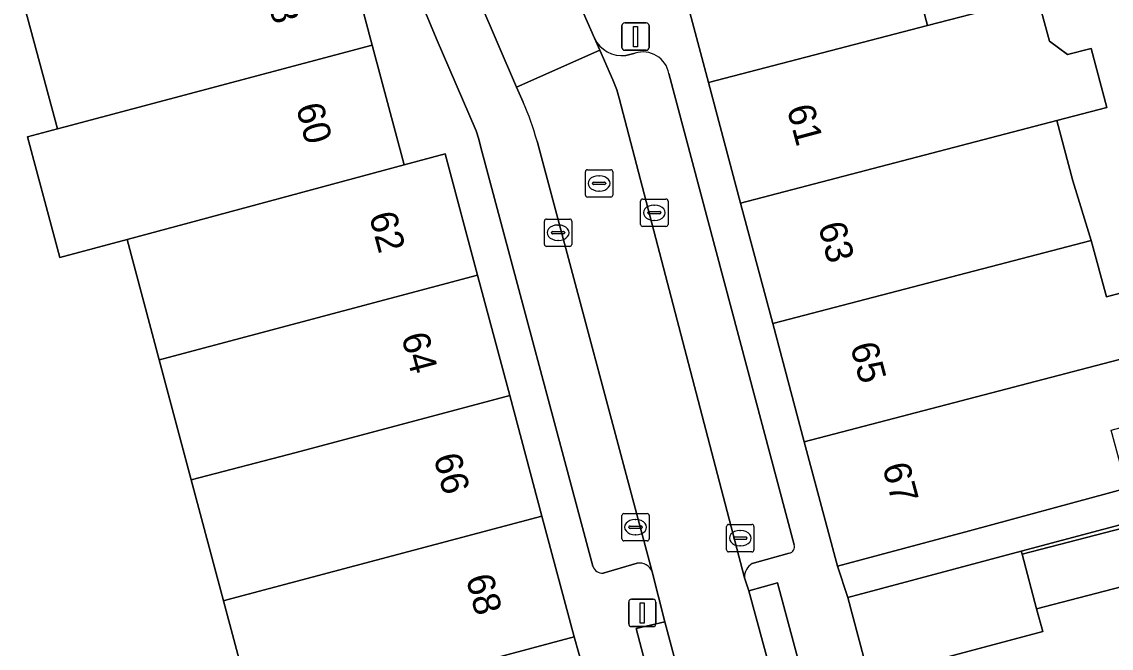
# Model space of a CAD drawing. Extents: x 162542 to 163147, y 380779 to 381521.
# Drawn here: x 162882.07 to 162921.91, y 380905.79 to 380928.7 of the extents above; entities that cross this region are included whole.
import ezdxf

# ---------------------------------------------------------------- set-up
doc = ezdxf.new("R2010")
doc.units = 0
for name, color, linetype in [('IMGEO_Erf', 7, 'Continuous'), ('IMGEO_Kolk', 7, 'Continuous'), ('IMGEO_Lichtmast', 7, 'Continuous'), ('IMGEO_Pand', 7, 'Continuous'), ('IMGEO_Pand_nummerreeks', 7, 'Continuous'), ('IMGEO_Parkeervlak_open', 7, 'Continuous'), ('IMGEO_Rijbaan_lokaal_open', 7, 'Continuous'), ('IMGEO_Rioolput', 7, 'Continuous'), ('IMGEO_Voetpad_open', 7, 'Continuous')]:
    doc.layers.add(name, color=color, linetype=linetype)

msp = doc.modelspace()

# ---------------------------------------------------------------- linework, layer by layer
at = {"layer": 'IMGEO_Erf'}
for points in [[(162890.631, 380903.092), (162889.449, 380907.52), (162888.269, 380911.939), (162887.097, 380916.331), (162885.922, 380920.733), (162883.467, 380920.075), (162882.284, 380924.488), (162883.382, 380924.781), (162882.176, 380929.207), (162880.985, 380933.581)], [(162914.667, 380930.542), (162915.195, 380928.561), (162919.214, 380929.61), (162919.648, 380927.984), (162920.311, 380927.498), (162921.176, 380927.724), (162921.753, 380925.561), (162919.917, 380925.082), (162920.505, 380922.876), (162921.182, 380920.701), (162921.733, 380918.636), (162923.471, 380919.099)], [(162945.042, 380916.372), (162918.622, 380909.332), (162918.65, 380909.228), (162923.026, 380910.365)], [(162923.547, 380908.361), (162919.184, 380907.225), (162919.405, 380906.398), (162913.056, 380904.704), (162914.099, 380900.681), (162917.41, 380901.57), (162920.403, 380902.374), (162920.845, 380900.718), (162926.157, 380902.145)]]:
    msp.add_lwpolyline(points, dxfattribs=at)
at = {"layer": 'IMGEO_Kolk'}
for p, q in [((162904.701, 380921.287), (162904.701, 380922.139)), ((162904.776, 380922.213), (162905.628, 380922.213)), ((162905.702, 380922.139), (162905.702, 380921.287)), ((162904.96, 380921.707), (162904.96, 380921.719)), ((162905.398, 380921.67), (162905, 380921.67)), ((162905.003, 380921.756), (162905.401, 380921.756)), ((162905.189, 380921.993), (162905.214, 380921.993)), ((162905.444, 380921.719), (162905.444, 380921.707)), ((162901.182, 380920.557), (162901.182, 380921.409)), ((162901.257, 380921.483), (162902.109, 380921.483)), ((162901.67, 380921.263), (162901.695, 380921.263)), ((162902.183, 380921.409), (162902.183, 380920.557)), ((162905.212, 380921.433), (162905.187, 380921.433)), ((162901.441, 380920.977), (162901.441, 380920.989)), ((162901.879, 380920.94), (162901.481, 380920.94)), ((162901.484, 380921.026), (162901.882, 380921.026)), ((162901.925, 380920.989), (162901.925, 380920.977)), ((162905.628, 380921.213), (162904.776, 380921.213)), ((162902.109, 380920.483), (162901.257, 380920.483)), ((162901.693, 380920.703), (162901.668, 380920.703)), ((162904.015, 380909.786), (162904.015, 380910.638)), ((162904.09, 380910.712), (162904.942, 380910.712)), ((162905.016, 380910.638), (162905.016, 380909.786)), ((162904.274, 380910.206), (162904.274, 380910.218)), ((162904.712, 380910.169), (162904.314, 380910.169)), ((162904.317, 380910.255), (162904.715, 380910.255)), ((162904.503, 380910.492), (162904.528, 380910.492)), ((162904.758, 380910.218), (162904.758, 380910.206)), ((162907.845, 380909.385), (162907.845, 380910.237)), ((162907.92, 380910.311), (162908.772, 380910.311)), ((162908.846, 380910.237), (162908.846, 380909.385)), ((162904.942, 380909.712), (162904.09, 380909.712)), ((162904.526, 380909.932), (162904.501, 380909.932)), ((162908.104, 380909.805), (162908.104, 380909.817)), ((162908.542, 380909.768), (162908.144, 380909.768)), ((162908.147, 380909.854), (162908.545, 380909.854)), ((162908.333, 380910.091), (162908.358, 380910.091)), ((162908.588, 380909.817), (162908.588, 380909.805)), ((162908.772, 380909.311), (162907.92, 380909.311)), ((162908.356, 380909.531), (162908.331, 380909.531))]:
    msp.add_line(p, q, dxfattribs=at)
for points in [[(162904.701, 380921.287), (162904.701, 380922.139)], [(162904.776, 380922.213), (162905.628, 380922.213)], [(162905.702, 380922.139), (162905.702, 380921.287)], [(162901.182, 380920.557), (162901.182, 380921.409)], [(162901.257, 380921.483), (162902.109, 380921.483)], [(162902.183, 380921.409), (162902.183, 380920.557)], [(162905.628, 380921.213), (162904.776, 380921.213)], [(162902.109, 380920.483), (162901.257, 380920.483)], [(162904.015, 380909.786), (162904.015, 380910.638)], [(162904.09, 380910.712), (162904.942, 380910.712)], [(162905.016, 380910.638), (162905.016, 380909.786)], [(162907.845, 380909.385), (162907.845, 380910.237)], [(162907.92, 380910.311), (162908.772, 380910.311)], [(162908.846, 380910.237), (162908.846, 380909.385)], [(162904.942, 380909.712), (162904.09, 380909.712)], [(162908.772, 380909.311), (162907.92, 380909.311)]]:
    msp.add_lwpolyline(points, dxfattribs=at)
for centre, radius, start, end in [((162904.778, 380922.137), 0.0765, 91.552, 178.448), ((162904.778, 380922.137), 0.0765, 91.552, 178.448), ((162905.626, 380922.137), 0.0765, 1.552, 88.448), ((162905.626, 380922.137), 0.0765, 1.552, 88.448), ((162905, 380921.716), 0.0403, 85.8775, 175.7526), ((162904.997, 380921.706), 0.0366, 178.938, 274.7102), ((162905.401, 380921.713), 0.043, 264.8664, 352.4533), ((162905.405, 380921.718), 0.0386, 1.7309, 96.639), ((162901.259, 380921.407), 0.0765, 91.552, 178.448), ((162901.259, 380921.407), 0.0765, 91.552, 178.448), ((162902.107, 380921.407), 0.0765, 1.552, 88.448), ((162902.107, 380921.407), 0.0765, 1.552, 88.448), ((162904.778, 380921.289), 0.0765, 181.552, 268.448), ((162904.778, 380921.289), 0.0765, 181.552, 268.448), ((162905.626, 380921.289), 0.0765, 271.552, 358.448), ((162905.626, 380921.289), 0.0765, 271.552, 358.448), ((162901.481, 380920.986), 0.0403, 85.8775, 175.7526), ((162901.478, 380920.976), 0.0366, 178.938, 274.7102), ((162901.882, 380920.983), 0.043, 264.8664, 352.4533), ((162901.886, 380920.988), 0.0386, 1.7309, 96.639), ((162901.259, 380920.559), 0.0765, 181.552, 268.448), ((162901.259, 380920.559), 0.0765, 181.552, 268.448), ((162902.107, 380920.559), 0.0765, 271.552, 358.448), ((162902.107, 380920.559), 0.0765, 271.552, 358.448), ((162904.092, 380910.636), 0.0765, 91.552, 178.448), ((162904.092, 380910.636), 0.0765, 91.552, 178.448), ((162904.94, 380910.636), 0.0765, 1.552, 88.448), ((162904.94, 380910.636), 0.0765, 1.552, 88.448), ((162904.314, 380910.215), 0.0403, 85.8775, 175.7526), ((162904.311, 380910.205), 0.0366, 178.938, 274.7102), ((162904.715, 380910.212), 0.043, 264.8664, 352.4533), ((162904.719, 380910.217), 0.0386, 1.7309, 96.639), ((162907.922, 380910.235), 0.0765, 91.552, 178.448), ((162907.922, 380910.235), 0.0765, 91.552, 178.448), ((162908.77, 380910.235), 0.0765, 1.552, 88.448), ((162908.77, 380910.235), 0.0765, 1.552, 88.448), ((162904.092, 380909.788), 0.0765, 181.552, 268.448), ((162904.092, 380909.788), 0.0765, 181.552, 268.448), ((162904.94, 380909.788), 0.0765, 271.552, 358.448), ((162904.94, 380909.788), 0.0765, 271.552, 358.448), ((162908.144, 380909.814), 0.0403, 85.8775, 175.7526), ((162908.141, 380909.804), 0.0366, 178.938, 274.7102), ((162908.545, 380909.811), 0.043, 264.8664, 352.4533), ((162908.549, 380909.816), 0.0386, 1.7309, 96.639), ((162907.922, 380909.387), 0.0765, 181.552, 268.448), ((162907.922, 380909.387), 0.0765, 181.552, 268.448), ((162908.77, 380909.387), 0.0765, 271.552, 358.448), ((162908.77, 380909.387), 0.0765, 271.552, 358.448)]:
    msp.add_arc(centre, radius, start, end, dxfattribs=at)
for centre, major_axis, ratio, start_param, end_param in [((162905.188, 380921.713), (-0.387, 0.002), 0.722429, 4.712389, 7.853982), ((162905.213, 380921.713), (-0.39, 0.002), 0.717154, 1.570796, 4.712389), ((162901.669, 380920.983), (-0.387, 0.002), 0.722429, 4.712389, 7.853982), ((162901.694, 380920.983), (-0.39, 0.002), 0.717154, 1.570796, 4.712389), ((162904.502, 380910.212), (-0.387, 0.002), 0.722429, 4.712389, 7.853982), ((162904.527, 380910.212), (-0.39, 0.002), 0.717154, 1.570796, 4.712389), ((162908.332, 380909.811), (-0.387, 0.002), 0.722429, 4.712389, 7.853982), ((162908.357, 380909.811), (-0.39, 0.002), 0.717154, 1.570796, 4.712389)]:
    msp.add_ellipse(centre, major_axis=major_axis, ratio=ratio, start_param=start_param, end_param=end_param, dxfattribs=at)
at = {"layer": 'IMGEO_Lichtmast'}
for p, q in [((162904.019, 380927.755), (162904.019, 380928.555)), ((162904.019, 380928.555), (162904.019, 380927.755)), ((162904.119, 380928.655), (162904.909, 380928.655)), ((162904.909, 380928.655), (162904.119, 380928.655)), ((162905.009, 380928.555), (162905.009, 380927.755)), ((162905.009, 380927.755), (162905.009, 380928.555)), ((162904.909, 380927.655), (162904.119, 380927.655)), ((162904.119, 380927.655), (162904.909, 380927.655)), ((162904.266, 380906.676), (162904.266, 380907.476)), ((162904.266, 380907.476), (162904.266, 380906.676)), ((162904.366, 380907.576), (162905.156, 380907.576)), ((162905.156, 380907.576), (162904.366, 380907.576)), ((162905.256, 380907.476), (162905.256, 380906.676)), ((162905.256, 380906.676), (162905.256, 380907.476)), ((162905.156, 380906.576), (162904.366, 380906.576)), ((162904.366, 380906.576), (162905.156, 380906.576))]:
    msp.add_line(p, q, dxfattribs=at)
for points in [[(162904.439, 380928.53), (162904.589, 380928.53), (162904.589, 380927.78), (162904.439, 380927.78), (162904.439, 380928.53)], [(162904.686, 380907.451), (162904.836, 380907.451), (162904.836, 380906.701), (162904.686, 380906.701), (162904.686, 380907.451)]]:
    msp.add_lwpolyline(points, dxfattribs=at)
for centre, start, end in [((162904.119, 380928.555), 90, 180), ((162904.119, 380928.555), 90, 180), ((162904.909, 380928.555), 0, 90), ((162904.909, 380928.555), 360, 90), ((162904.119, 380927.755), 180, 270), ((162904.119, 380927.755), 180, 270), ((162904.909, 380927.755), 270, 0), ((162904.909, 380927.755), 270, 0), ((162904.366, 380907.476), 90, 180), ((162904.366, 380907.476), 90, 180), ((162905.156, 380907.476), 0, 90), ((162905.156, 380907.476), 360, 90), ((162904.366, 380906.676), 180, 270), ((162904.366, 380906.676), 180, 270), ((162905.156, 380906.676), 270, 0), ((162905.156, 380906.676), 270, 0)]:
    msp.add_arc(centre, 0.1, start, end, dxfattribs=at)
at = {"layer": 'IMGEO_Pand'}
for points in [[(162906.008, 380930.874), (162907.183, 380926.47), (162915.195, 380928.561), (162914.667, 380930.542), (162918.176, 380931.478), (162917.534, 380933.883)], [(162894.884, 380927.843), (162893.708, 380932.249), (162882.176, 380929.207), (162883.382, 380924.781), (162883.653, 380924.853)], [(162921.176, 380927.724), (162920.311, 380927.498), (162919.648, 380927.984), (162919.214, 380929.61), (162915.195, 380928.561), (162907.183, 380926.47), (162908.358, 380922.065), (162919.917, 380925.082), (162921.753, 380925.561)], [(162885.922, 380920.733), (162888.504, 380921.425), (162896.052, 380923.468), (162894.884, 380927.843), (162883.653, 380924.853), (162883.382, 380924.781), (162882.284, 380924.488), (162883.467, 380920.075)], [(162919.917, 380925.082), (162908.358, 380922.065), (162909.533, 380917.661), (162921.182, 380920.701), (162920.505, 380922.876)], [(162885.922, 380920.733), (162887.097, 380916.331), (162887.236, 380916.369), (162898.741, 380919.432), (162897.556, 380923.869), (162896.052, 380923.468), (162888.504, 380921.425)], [(162921.182, 380920.701), (162909.533, 380917.661), (162910.687, 380913.334), (162924.075, 380916.835), (162923.471, 380919.099), (162921.733, 380918.636)], [(162888.269, 380911.939), (162892.108, 380912.947), (162899.917, 380915.027), (162898.741, 380919.432), (162887.236, 380916.369), (162887.097, 380916.331)], [(162924.075, 380916.835), (162910.687, 380913.334), (162911.899, 380908.789), (162916.731, 380910.078), (162919.873, 380910.937), (162922.48, 380911.639), (162921.913, 380913.766), (162922.957, 380914.045), (162924.696, 380914.509)], [(162889.449, 380907.52), (162889.573, 380907.553), (162901.093, 380910.62), (162899.917, 380915.027), (162892.108, 380912.947), (162888.269, 380911.939)], [(162889.449, 380907.52), (162890.631, 380903.092), (162897.443, 380904.91), (162902.273, 380906.2), (162901.093, 380910.62), (162889.573, 380907.553)], [(162924.873, 380910.845), (162923.026, 380910.365), (162918.65, 380909.228), (162919.184, 380907.225), (162923.547, 380908.361), (162925.406, 380908.845)], [(162919.184, 380907.225), (162918.65, 380909.228), (162918.622, 380909.332), (162912.273, 380907.638), (162913.056, 380904.704), (162919.405, 380906.398)]]:
    msp.add_lwpolyline(points, close=True, dxfattribs=at)
at = {"layer": 'IMGEO_Parkeervlak_open'}
for points in [[(162863.623, 381056.326), (162869.619, 381033.902), (162872.201, 381021.07), (162882.251, 380983.223), (162896.332, 380930.722), (162896.579, 380929.758), (162896.835, 380929.036), (162897.228, 380928.095), (162898.683, 380924.706), (162898.786, 380924.4), (162898.843, 380924.15), (162902.951, 380908.79)], [(162900.404, 380925.757), (162900.167, 380926.307), (162898.784, 380929.52), (162898.75, 380929.6)], [(162903.018, 380928.1), (162903.211, 380927.653), (162903.679, 380926.571), (162903.826, 380926.209), (162903.922, 380925.897), (162908.496, 380908.364)], [(162904.497, 380927.552), (162904.154, 380927.467)], [(162910.311, 380909.571), (162905.736, 380926.804)], [(162905.118, 380908.579), (162900.912, 380924.329)], [(162908.786, 380908.882), (162910.137, 380909.259)], [(162903.337, 380908.533), (162904.57, 380908.891)]]:
    msp.add_lwpolyline(points, dxfattribs=at)
for centre, radius, start, end in [((162904.01, 380928.544), 1.086, 204.1126, 277.6327), ((162904.782, 380926.624), 0.971, 10.6923, 107.0679), ((162891.503, 380921.786), 9.747, 15.1231, 24.0421), ((162910.092, 380909.489), 0.234, 281.0833, 20.6206), ((162904.662, 380908.415), 0.485, 19.8, 100.8905), ((162903.303, 380908.9), 0.369, 197.3729, 275.3155), ((162909.073, 380908.381), 0.578, 119.8374, 181.6784)]:
    msp.add_arc(centre, radius, start, end, dxfattribs=at)
at = {"layer": 'IMGEO_Rijbaan_lokaal_open'}
msp.add_lwpolyline([(162901.98, 380930.5), (162901.876, 380930.848), (162898.784, 380929.52), (162900.167, 380926.307), (162903.211, 380927.653), (162903.018, 380928.1), (162902.029, 380930.351)], close=True, dxfattribs=at)
for points in [[(162908.657, 380907.882), (162908.496, 380908.364), (162903.922, 380925.897), (162903.826, 380926.209), (162903.679, 380926.571), (162903.211, 380927.653), (162900.167, 380926.307), (162900.404, 380925.757)], [(162900.912, 380924.329), (162905.118, 380908.579), (162905.591, 380906.748), (162906.892, 380901.868), (162907.616, 380899.205), (162911.965, 380882.844), (162912.054, 380882.422), (162915.322, 380883.284), (162915.164, 380883.698), (162910.325, 380901.789), (162910.301, 380901.82), (162908.657, 380907.882)]]:
    msp.add_lwpolyline(points, dxfattribs=at)
msp.add_arc((162891.503, 380921.786), 9.747, 15.1231, 24.0421, dxfattribs=at)
at = {"layer": 'IMGEO_Rioolput'}
for p, q in [((162902.756, 380923.286), (162903.608, 380923.286)), ((162902.681, 380922.36), (162902.681, 380923.212)), ((162903.169, 380923.066), (162903.194, 380923.066)), ((162903.682, 380923.212), (162903.682, 380922.36)), ((162902.94, 380922.78), (162902.94, 380922.792)), ((162903.378, 380922.743), (162902.98, 380922.743)), ((162902.983, 380922.829), (162903.381, 380922.829)), ((162903.192, 380922.506), (162903.167, 380922.506)), ((162903.424, 380922.792), (162903.424, 380922.78)), ((162903.608, 380922.286), (162902.756, 380922.286))]:
    msp.add_line(p, q, dxfattribs=at)
for points in [[(162902.756, 380923.286), (162903.608, 380923.286)], [(162902.681, 380922.36), (162902.681, 380923.212)], [(162903.682, 380923.212), (162903.682, 380922.36)], [(162903.608, 380922.286), (162902.756, 380922.286)]]:
    msp.add_lwpolyline(points, dxfattribs=at)
for centre, radius, start, end in [((162902.758, 380923.21), 0.0765, 91.552, 178.448), ((162902.758, 380923.21), 0.0765, 91.552, 178.448), ((162903.606, 380923.21), 0.0765, 1.552, 88.448), ((162903.606, 380923.21), 0.0765, 1.552, 88.448), ((162902.98, 380922.789), 0.0403, 85.8775, 175.7526), ((162902.977, 380922.779), 0.0366, 178.938, 274.7102), ((162903.381, 380922.786), 0.043, 264.8664, 352.4533), ((162903.385, 380922.791), 0.0386, 1.7309, 96.639), ((162902.758, 380922.362), 0.0765, 181.552, 268.448), ((162902.758, 380922.362), 0.0765, 181.552, 268.448), ((162903.606, 380922.362), 0.0765, 271.552, 358.448), ((162903.606, 380922.362), 0.0765, 271.552, 358.448)]:
    msp.add_arc(centre, radius, start, end, dxfattribs=at)
for centre, major_axis, ratio, start_param, end_param in [((162903.168, 380922.786), (-0.387, 0.002), 0.722429, 4.712389, 7.853982), ((162903.193, 380922.786), (-0.39, 0.002), 0.717154, 1.570796, 4.712389)]:
    msp.add_ellipse(centre, major_axis=major_axis, ratio=ratio, start_param=start_param, end_param=end_param, dxfattribs=at)
at = {"layer": 'IMGEO_Voetpad_open'}
for points in [[(162917.907, 380886.554), (162916.944, 380890.084), (162914.099, 380900.681), (162913.056, 380904.704), (162912.273, 380907.638), (162911.899, 380908.789), (162910.687, 380913.334), (162909.533, 380917.661), (162908.358, 380922.065), (162907.183, 380926.47), (162906.008, 380930.874), (162904.833, 380935.28), (162903.739, 380939.382), (162902.548, 380943.847), (162901.348, 380948.349), (162900.298, 380952.285), (162899.145, 380956.607), (162897.983, 380960.964), (162896.838, 380965.255), (162895.656, 380969.686), (162894.511, 380973.981), (162893.132, 380979.151), (162892.932, 380979.9), (162891.804, 380984.13)], [(162886.651, 380958.683), (162887.828, 380954.277), (162889.003, 380949.872), (162890.18, 380945.466), (162891.356, 380941.06), (162892.532, 380936.654), (162893.708, 380932.249), (162894.884, 380927.843), (162896.052, 380923.468), (162897.556, 380923.869), (162898.741, 380919.432), (162899.917, 380915.027), (162901.093, 380910.62), (162902.273, 380906.2), (162902.59, 380905.075)], [(162902.951, 380908.79), (162898.843, 380924.15), (162898.786, 380924.4), (162898.683, 380924.706), (162897.228, 380928.095), (162896.835, 380929.036), (162896.579, 380929.758), (162896.332, 380930.722)], [(162901.957, 380930.656), (162901.98, 380930.5), (162902.029, 380930.351), (162903.018, 380928.1)], [(162904.154, 380927.467), (162904.497, 380927.552)], [(162905.736, 380926.804), (162910.311, 380909.571)], [(162922.48, 380911.639), (162919.873, 380910.937), (162916.731, 380910.078), (162911.899, 380908.789), (162912.273, 380907.638), (162918.622, 380909.332), (162945.042, 380916.372)], [(162910.137, 380909.259), (162908.786, 380908.882)], [(162904.57, 380908.891), (162903.337, 380908.533)], [(162907.616, 380899.205), (162906.892, 380901.868), (162905.836, 380901.584), (162904.538, 380906.507), (162905.591, 380906.748), (162905.118, 380908.579)], [(162908.496, 380908.364), (162908.657, 380907.882), (162909.711, 380908.174), (162911.341, 380902.089), (162910.301, 380901.82), (162910.325, 380901.789)], [(162902.59, 380905.075), (162902.273, 380906.2), (162897.443, 380904.91)]]:
    msp.add_lwpolyline(points, dxfattribs=at)
for points in [[(162908.657, 380907.882), (162910.301, 380901.82), (162911.341, 380902.089), (162909.711, 380908.174)], [(162905.591, 380906.748), (162904.538, 380906.507), (162905.836, 380901.584), (162906.892, 380901.868)]]:
    msp.add_lwpolyline(points, close=True, dxfattribs=at)
for centre, radius, start, end in [((162904.01, 380928.544), 1.086, 204.1126, 277.6327), ((162904.782, 380926.624), 0.971, 10.6923, 107.0679), ((162910.092, 380909.489), 0.234, 281.0833, 20.6206), ((162904.662, 380908.415), 0.485, 19.8, 100.8905), ((162903.303, 380908.9), 0.369, 197.3729, 275.3155), ((162909.073, 380908.381), 0.578, 119.8374, 181.6784)]:
    msp.add_arc(centre, radius, start, end, dxfattribs=at)

# ---------------------------------------------------------------- texts
at = {"layer": 'IMGEO_Pand_nummerreeks'}
for s, rotation, p in [('58', 284.9455, (162890.914, 380929.996)), ('60', 284.9455, (162892.09, 380925.59)), ('61', 284.9368, (162910.04, 380925.535)), ('62', 284.9474, (162894.763, 380921.615)), ('63', 284.9344, (162911.186, 380921.243)), ('64', 284.9474, (162895.943, 380917.195)), ('65', 284.9344, (162912.36, 380916.841)), ('66', 284.9474, (162897.122, 380912.778)), ('67', 284.9344, (162913.534, 380912.438)), ('68', 284.9474, (162898.303, 380908.359))]:
    msp.add_text(s, height=1, rotation=rotation, dxfattribs=at).set_placement(p)

doc.saveas('drawing.dxf')
